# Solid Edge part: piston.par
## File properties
Author: Robert a Rhodes jr
Template: normal.par
Last saved by: Cadcim
Revision: 12
Application: Solid Edge
Accuracy: 0.99
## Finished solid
Body 1: solid body, 42 faces, 58 edges, 16 vertices.
  Faces by surface: cylinder 21, plane 20, torus 1
  Edges by curve: circle 40, intersection 10, line 8
Bounding box of the edges (mm; curved faces can reach further): 93.000 x 93.000 x 66.000, from (-46.5, -46.5, -46) to (46.5, 46.5, 20).
Cylindrical faces by radius (mm): R10 x2, R15 x2, R19 x2, R37 x2, R38.5 x2, R42.5 x5, R46.5 x6
Toroidal faces (ring radius, tube radius in mm): R-5.5431 r189 x1
Planar faces by outward normal: +y 2, +z 7, -y 2, -z 9
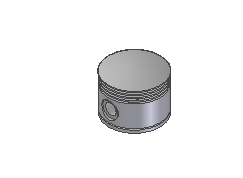
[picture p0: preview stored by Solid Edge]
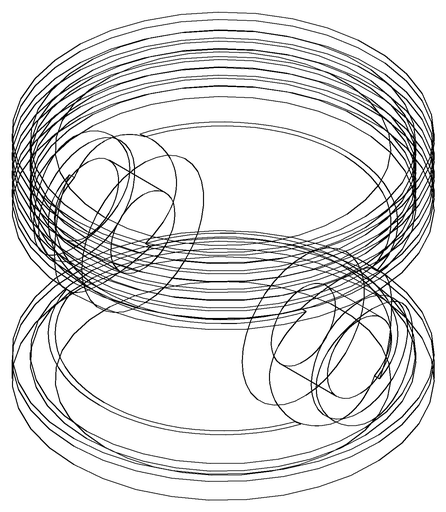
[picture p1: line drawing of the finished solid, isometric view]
